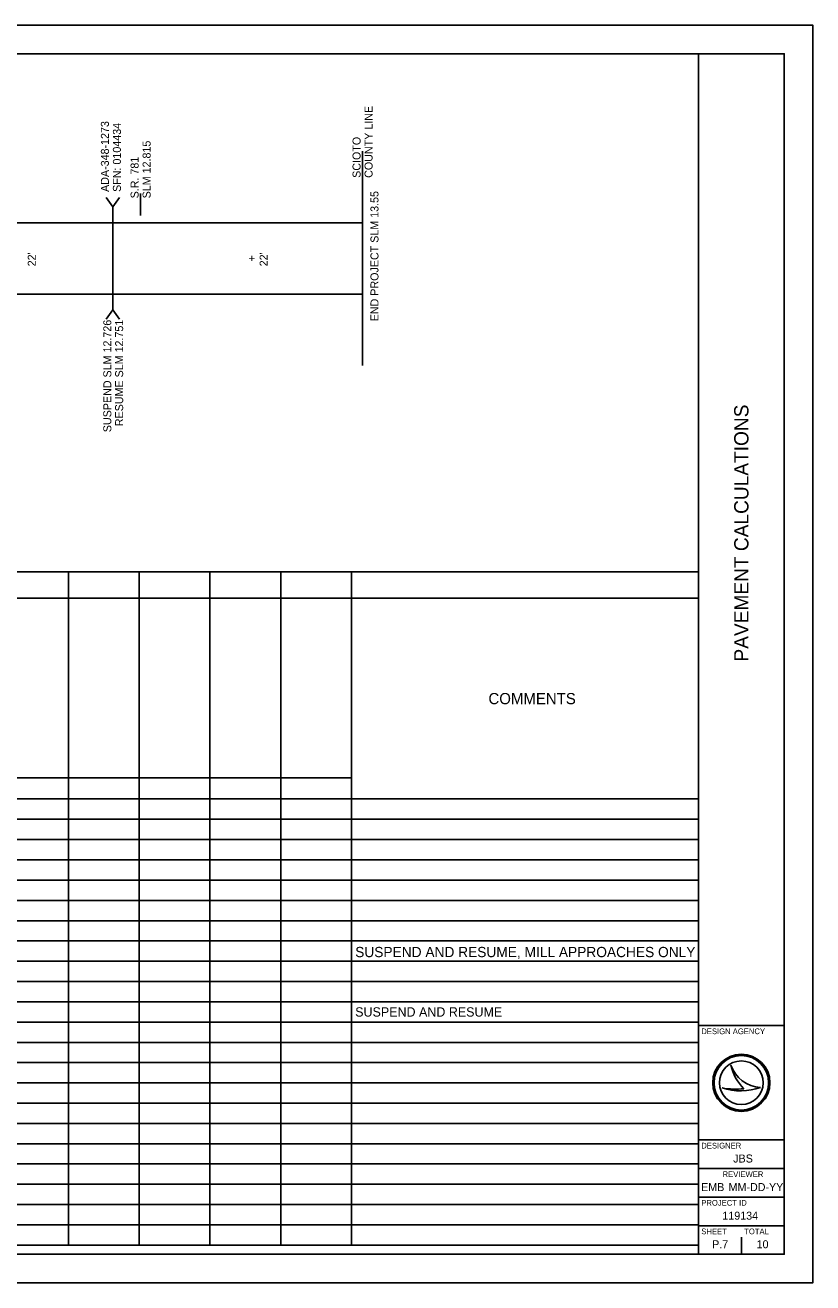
# Model space of a CAD drawing. Extents: x 0 to 34, y 0 to 22.
# Drawn here: x 20.23 to 34, y 0 to 22 of the extents above; entities that cross this region are included whole.
import ezdxf

# ---------------------------------------------------------------- set-up
doc = ezdxf.new("R2010")
doc.units = 0
for name, color, linetype in [('Default', 7, 'Continuous'), ('SH_Border', 7, 'Continuous'), ('SH_Cut_Line', 7, 'Continuous'), ('SH_Data', 7, 'Continuous'), ('SH_Text', 7, 'Continuous')]:
    doc.layers.add(name, color=color, linetype=linetype)

msp = doc.modelspace()

# ---------------------------------------------------------------- linework, layer by layer
at = {"layer": 'Default'}
for p, q in [((1.5, 21.5), (32, 21.5)), ((32, 21.5), (32, 0.66)), ((16.03, 12.437), (32, 12.437)), ((20.987, 12.437), (20.987, 0.66)), ((22.224, 12.437), (22.224, 0.66)), ((23.46, 12.437), (23.46, 0.66)), ((24.696, 12.437), (24.696, 0.66)), ((25.933, 12.437), (25.933, 0.66)), ((16.052, 11.976), (32, 11.976)), ((16.052, 8.836), (25.933, 8.836)), ((16.052, 8.464), (32, 8.464)), ((16.052, 8.109), (32, 8.109)), ((16.052, 7.754), (32, 7.754)), ((16.052, 7.4), (32, 7.4)), ((16.052, 7.045), (32, 7.045)), ((16.052, 6.69), (32, 6.69)), ((16.052, 6.335), (32, 6.335)), ((16.052, 5.981), (32, 5.981)), ((16.052, 5.626), (32, 5.626)), ((16.052, 5.271), (32, 5.271)), ((16.052, 4.916), (32, 4.916)), ((16.052, 4.562), (32, 4.562)), ((16.052, 4.207), (32, 4.207)), ((16.052, 3.852), (32, 3.852)), ((16.052, 3.498), (32, 3.498)), ((16.052, 3.143), (32, 3.143)), ((16.052, 2.788), (32, 2.788)), ((16.052, 2.433), (32, 2.433)), ((16.052, 2.079), (32, 2.079)), ((16.052, 1.724), (32, 1.724)), ((16.052, 1.369), (32, 1.369)), ((16.052, 1.014), (32, 1.014)), ((16.03, 0.66), (32, 0.66))]:
    msp.add_line(p, q, dxfattribs=at)
for points in [[(19.48, 18.545), (21.761, 18.545), (21.761, 17.295), (19.48, 17.295)], [(21.761, 18.545), (26.128, 18.545), (26.128, 17.295), (21.761, 17.295)]]:
    msp.add_lwpolyline(points, close=True, dxfattribs=at)
at = {"layer": 'SH_Border'}
for p, q in [((32, 0.5), (32, 21.5)), ((32, 4.5), (33.5, 4.5)), ((32, 2.5), (33.5, 2.5)), ((32, 2), (33.5, 2)), ((32, 1.5), (33.5, 1.5)), ((32, 1), (33.5, 1))]:
    msp.add_line(p, q, dxfattribs=at)
msp.add_lwpolyline([(1.5, 21.5), (33.5, 21.5), (33.5, 0.5), (1.5, 0.5)], close=True, dxfattribs=at)
at = {"layer": 'SH_Cut_Line'}
msp.add_lwpolyline([(0, 0), (34, 0), (34, 22), (0, 22)], close=True, dxfattribs=at)
at = {"layer": 'SH_Data'}
for p, q in [((32.567, 3.81), (32.567, 3.81)), ((32.417, 3.41), (32.417, 3.41)), ((32.75, 3.5), (32.75, 3.5)), ((33.087, 3.419), (33.087, 3.419)), ((32.375, 0.675), (32.375, 0.675)), ((32.75, 0.5), (32.75, 0.8))]:
    msp.add_line(p, q, dxfattribs=at)
for radius in [0.5, 0.477, 0.477, 0.382]:
    msp.add_circle((32.75, 3.5), radius, dxfattribs=at)
for centre, radius, start, end in [((33.116, 3.998), 0.58, 198.9257, 198.9319), ((33.347, 3.97), 0.796, 191.6379, 191.6421), ((33.116, 3.998), 0.58, 198.9319, 267.1657), ((33.347, 3.97), 0.796, 191.6421, 226.0947), ((32.739, 4.37), 1.013, 251.4576, 290.0832), ((32.648, 4.654), 1.266, 259.4964, 259.4995), ((32.739, 4.37), 1.013, 251.4527, 251.4576), ((32.648, 4.654), 1.266, 259.4995, 276.6672)]:
    msp.add_arc(centre, radius, start, end, dxfattribs=at)
at = {"layer": 'SH_Text'}
for p, q in [((26.128, 19.795), (26.128, 16.045)), ((21.761, 18.82), (21.647, 18.983)), ((21.761, 18.82), (21.876, 18.983)), ((22.247, 19.054), (22.247, 18.67)), ((21.761, 17.02), (21.761, 18.82)), ((7.384, 18.545), (26.128, 18.545)), ((22.247, 18.545), (22.122, 18.545)), ((22.247, 18.545), (22.372, 18.545)), ((7.384, 17.295), (26.128, 17.295)), ((21.761, 17.02), (21.647, 16.856)), ((21.761, 17.02), (21.876, 16.856))]:
    msp.add_line(p, q, dxfattribs=at)

# ---------------------------------------------------------------- texts
at = {"layer": 'Default'}
for s, height, p in [('COMMENTS', 0.1958, (28.329, 10.122)), ('SUSPEND AND RESUME, MILL APPROACHES ONLY', 0.17949, (25.999, 5.697)), ('SUSPEND AND RESUME', 0.16318, (25.999, 4.657))]:
    msp.add_text(s, height=height, dxfattribs=at).set_placement(p)
at = {"layer": 'SH_Data'}
msp.add_text('PAVEMENT CALCULATIONS', height=0.25, rotation=90, dxfattribs=at).set_placement((32.875, 10.868))
for s, height, p in [('DESIGN AGENCY', 0.1, (32.05, 4.35)), ('DESIGNER', 0.1, (32.05, 2.35)), ('JBS', 0.14, (32.608, 2.105)), ('REVIEWER', 0.1, (32.422, 1.85)), ('EMB', 0.14, (32.047, 1.605)), ('MM-DD-YY', 0.14, (32.527, 1.605)), ('PROJECT ID', 0.1, (32.05, 1.35)), ('119134', 0.14, (32.418, 1.105)), ('SHEET', 0.1, (32.05, 0.85)), ('TOTAL', 0.1, (32.8, 0.85)), ('P.7', 0.14, (32.239, 0.605)), ('10', 0.14, (33.017, 0.605))]:
    msp.add_text(s, height=height, dxfattribs=at).set_placement(p)
at = {"layer": 'SH_Text'}
for s, p in [('COUNTY LINE', (26.303, 19.329)), ('ADA-348-1273', (21.693, 19.083)), ('SFN: 0104434', (21.903, 19.083)), ('SCIOTO ', (26.093, 19.329)), ('SLM 12.815', (22.422, 18.97)), ('S.R. 781', (22.212, 18.97)), ('END PROJECT SLM 13.55', (26.406, 16.82)), ("22'", (20.414, 17.781)), ('+', (24.259, 17.867)), ("22'", (24.469, 17.781)), ('SUSPEND SLM 12.726', (21.735, 14.88)), ('RESUME SLM 12.751', (21.942, 14.985))]:
    msp.add_text(s, height=0.14, rotation=90, dxfattribs=at).set_placement(p)

doc.saveas('drawing.dxf')
